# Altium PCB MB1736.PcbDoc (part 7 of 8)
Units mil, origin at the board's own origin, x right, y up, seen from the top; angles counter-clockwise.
Board outline 5905.51 x 3779.53 mil, 6 copper layers (Top Layer, L2_GND, L3_SIG, L4_VCC, L5_GND, Bottom Layer), stack 117.811 mil thick; 481 components, 387 nets, 1904 pads, 1200 vias.
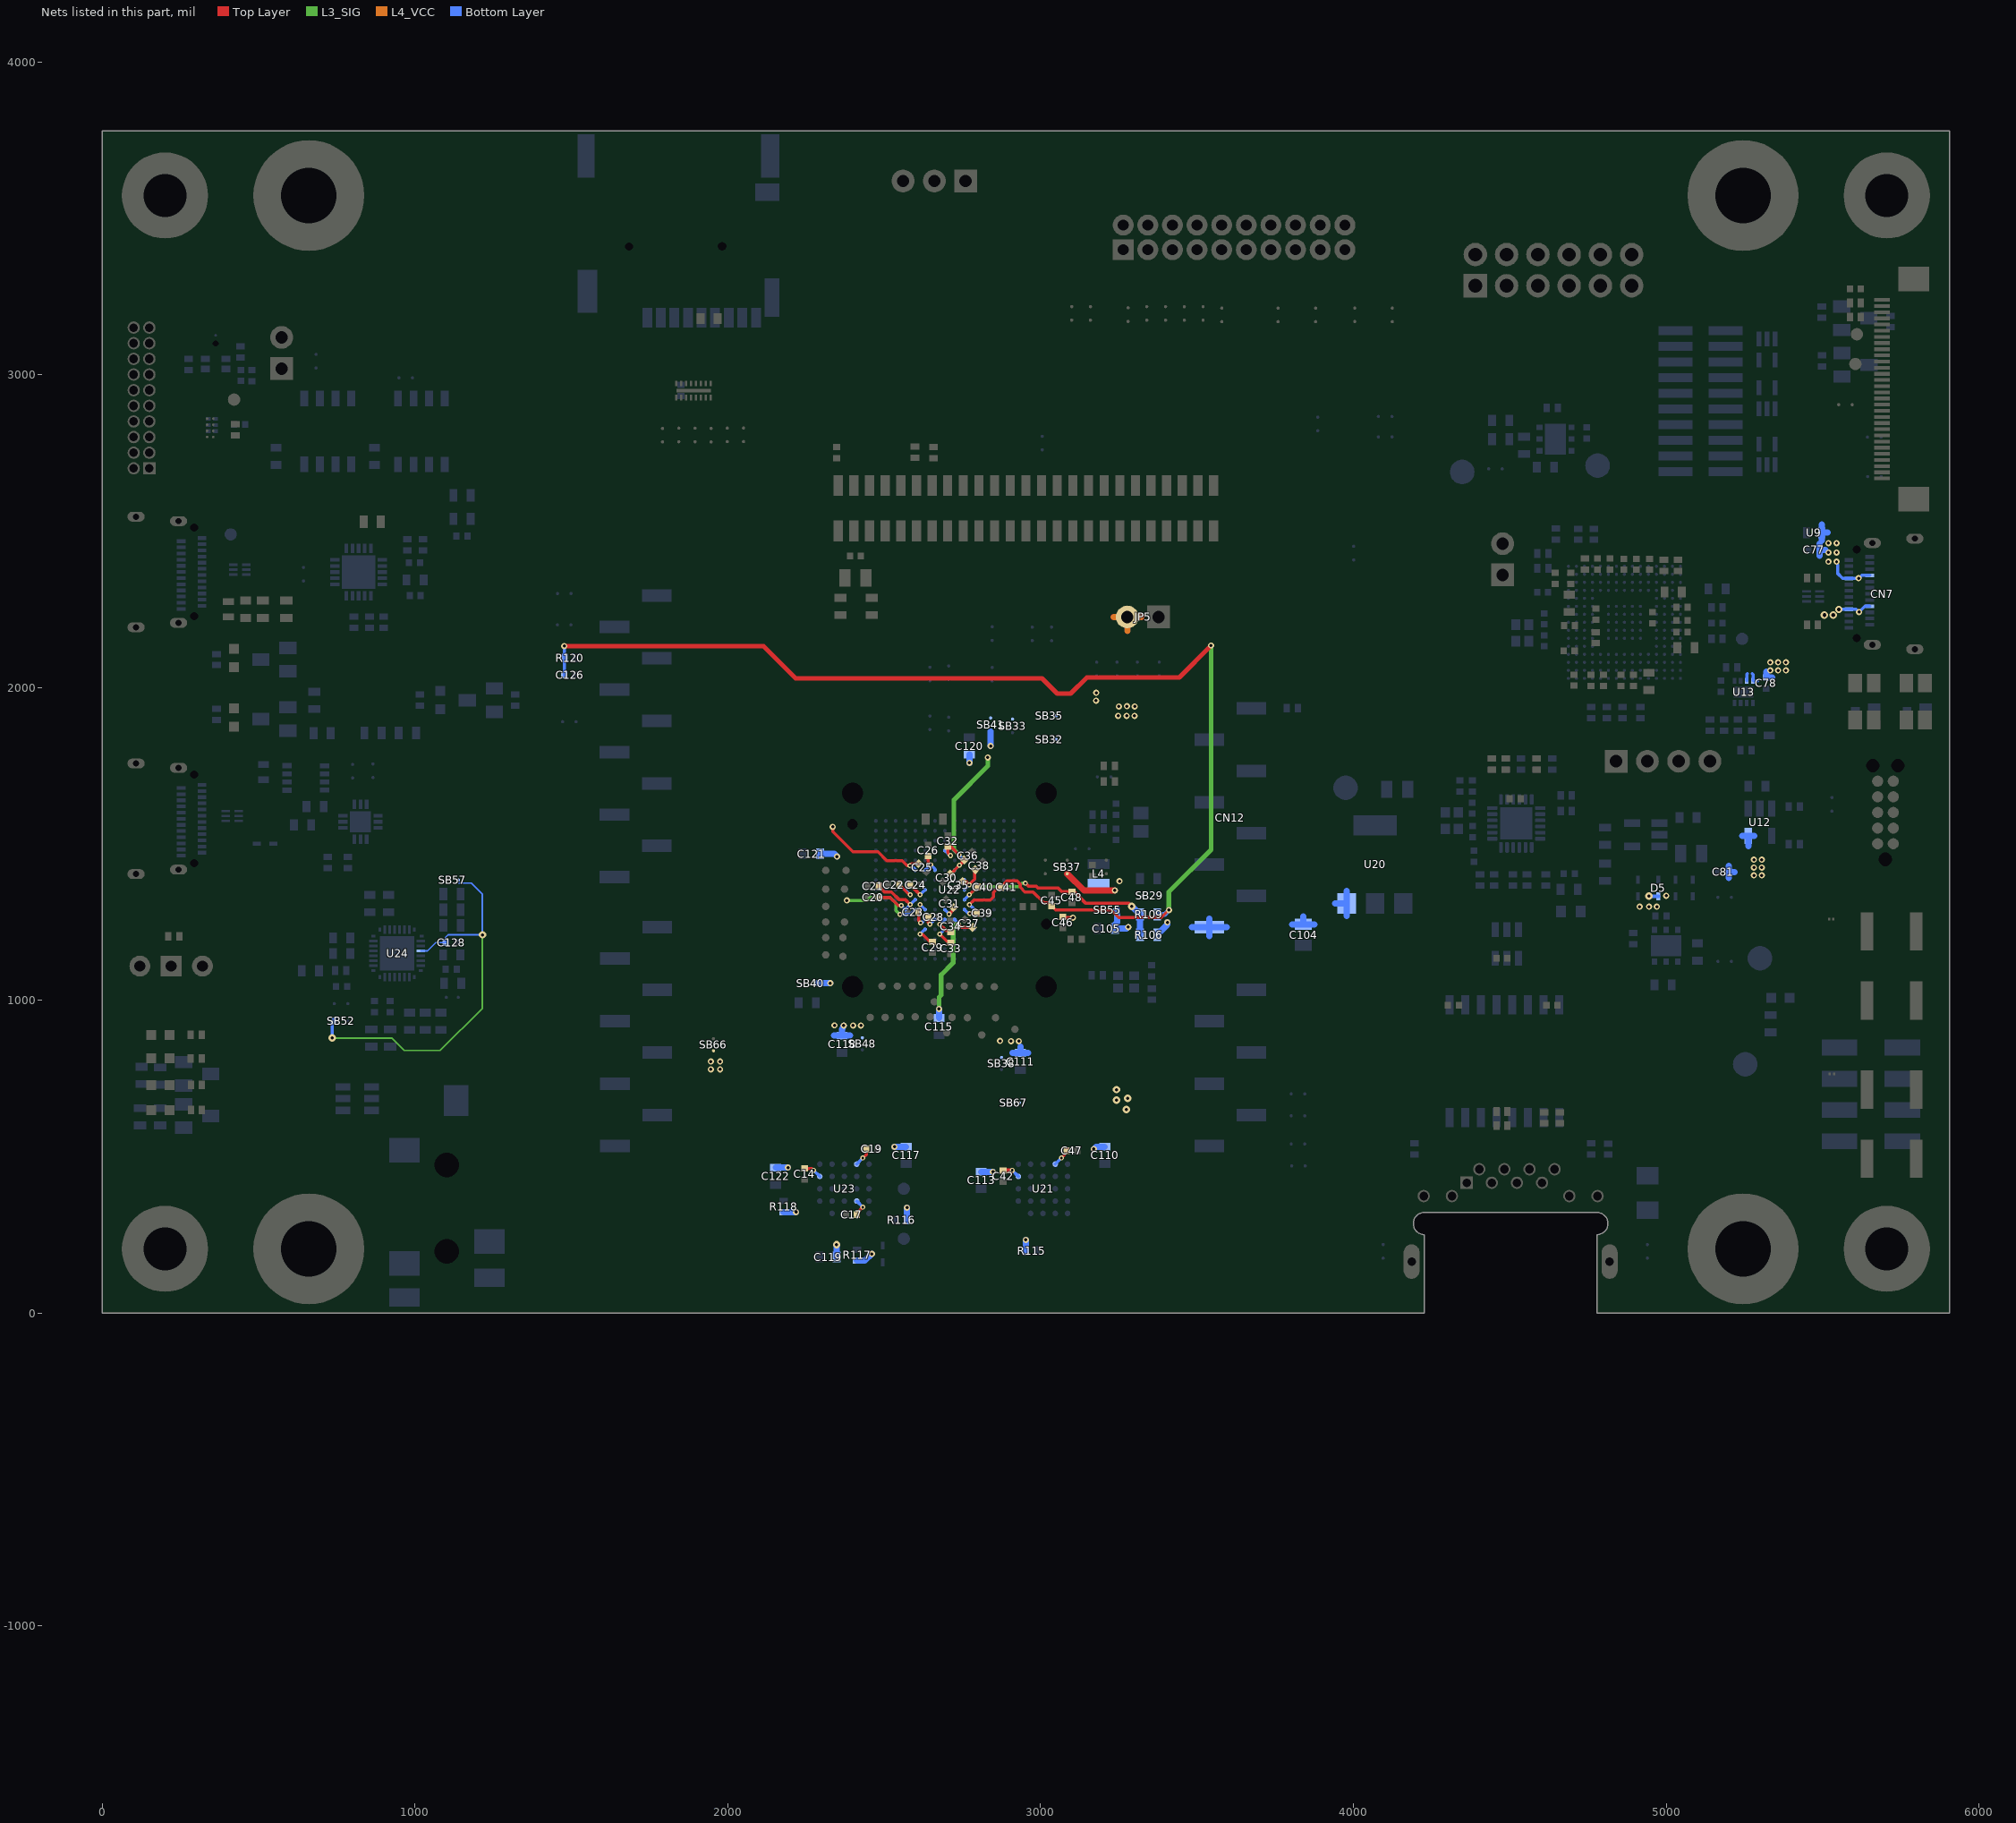
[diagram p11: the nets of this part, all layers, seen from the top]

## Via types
v1: diameter 20, hole 10, Top Layer to Bottom Layer, tented both sides, 518 vias
v2: diameter 16, hole 8, Top Layer to Bottom Layer, tented both sides, 311 vias
v3: diameter 24, hole 10, Top Layer to Bottom Layer, tented both sides, 301 vias
v4: diameter 24, hole 12, Top Layer to Bottom Layer, tented both sides, 61 vias
v5: diameter 23.62, hole 11.81, Top Layer to Bottom Layer, 9 vias

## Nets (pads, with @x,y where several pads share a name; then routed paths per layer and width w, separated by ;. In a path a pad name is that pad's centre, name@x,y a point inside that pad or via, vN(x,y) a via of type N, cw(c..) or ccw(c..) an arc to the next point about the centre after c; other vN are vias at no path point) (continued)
VBUS_STLK: C77.1 C78.1 C81.2 CN7.A4 CN7.A9 CN7.B4 CN7.B9 D5.1 U9.1 U12.5 U13.3 U13.4 | length 634.8
  Bottom Layer w10: U13.3@5257.9,2022.1 5257.88,2042.88 5260,2045 ; 5275,2045 5277.57,2042.42 U13.4@5277.58,2022.1 5292.91,2022.09 ; 5548,2392 5548,2366 5564.8,2349.2 CN7.A4@5584,2349.2 v1@5614.98,2349.21 ; v4(5552,2250) 5552.78,2250.78 CN7.A9@5584,2250.78 5607.73,2250.78 v1(5616.75,2241.75) 5635.61,2260.61 CN7.B4@5650.93,2260.62 ; v1@5616.76,2349.99 5625.83,2359.06 CN7.B9@5650.93,2359.05
  Bottom Layer w12: v3(4945,1333.42) D5.1@4975,1333.42
  Bottom Layer w20: 5200.48,1391.84 C81.2@5200.49,1410.9 ; 5200.48,1429.94 C81.2@5200.49,1410.9 ; 5218.54,1410.9 C81.2@5200.49,1410.9 ; 5242.77,1526.68 U12.5@5262.6,1526.68 ; 5262.6,1493.08 U12.5@5262.6,1526.68 ; 5282.43,1526.68 U12.5@5262.62,1526.69 ; 5320,2050.77 C78.1@5320,2032.71 5339.05,2032.72 ; 5490.49,2421.84 C77.1@5490.49,2440.9 ; 5490.49,2459.94 C77.1@5490.49,2440.9 ; 5497.38,2470.16 U9.1@5497.38,2495.9 ; 5497.38,2521.64 U9.1@5497.38,2495.9 ; 5508.55,2440.9 C77.1@5490.49,2440.9 ; 5516.23,2495.9 U9.1@5497.38,2495.9
  other v1: 4915,1300 4945,1300 4970,1300.05 5000,1335 5281,1400 5306,1400 5281,1425 5306,1425 5281,1450 5306,1450 5333,2055 5358,2055 5383,2055 5333,2081 5358,2081 5383,2081 5615.76,2349.99 5519,2403 5545,2403 5519,2432 5545,2432 5519,2462 5545,2462
  other v4: 5506,2232 5534,2232
VCAP: C25.2 C32.2 C37.2 C115.2 C120.2 C121.2 SB40.2 SB41.1 U22.D8 U22.E6 U22.F11 U22.K11 U22.L7 | length 1689.7
  Top Layer w10: v1(2335,1555) 2335,1540 2400,1475 2480,1475 2508.03,1446.97 2557.05,1446.97 2572.83,1431.18 v2(2582.28,1431.18) 2588.62,1437.52 C25.2@2609.49,1437.53 ; v2(2711.56,1463.41) 2703,1471.97 C32.2@2703,1492.3 2712.31,1492.3 v2(2738.81,1465.8) ; v2(2738,1243.5) 2748.04,1233.47 C37.2@2782.54,1233.48
  L3_SIG w10: v1(2380.5,1320) 2445,1320 2455,1330 2519,1330 2537.66,1311.34 2537.66,1287.34 v2(2550,1275)
  L3_SIG w15: v1(2674.86,973) 2675,973.14 2675,1010.76 2682,1017.76 2682,1081.99 2720,1119.99 2720,1232.89 2730.62,1243.5 v2(2738,1243.5) ; v2(2738.81,1465.8) 2722.13,1482.48 2722.13,1641.13 2831,1750 v1(2831,1777)
  Bottom Layer w10: v2(2550,1275) 2583.15,1275 U22.K11@2598.93,1290.76 ; U22.D8@2693.4,1479.73 2700.05,1473.08 2709.7,1463.41 v2(2711.56,1463.41) ; U22.L7@2724.9,1259.24 2738,1246.14 v2(2738,1243.5) ; v2(2738.81,1465.8) U22.E6@2756.37,1448.24
  Bottom Layer w12: v2(2582.28,1431.18) 2584.46,1431.18 U22.F11@2598.93,1416.75
  Bottom Layer w20: SB40.2@2286.31,1055 v1(2327,1055) ; C121.2@2294.44,1469 2340,1469 v1(2349,1460) ; v1(2674.86,973) 2675,972.86 C115.2@2675,944 ; v1(2772,1760) C120.2@2772,1786 ; v1(2840,1813.5) SB41.1@2840,1860.31
VDD_HEXASPI: C23.2 C29.2 C33.2 C34.2 C111.2 SB38.2 U22.L8 U22.L10 U22.M8 U22.M10 | length 338.2
  Top Layer w10: C23.2@2609.73,1282 2609.73,1254.8 v2(2616.3,1248.23) ; v2@2613.66,1211.01 v2@2614.66,1211.01 ; v2(2614.66,1212.01) v2@2614.66,1211.01 ; C29.2@2654,1187.73 2646.39,1187.73 2623.1,1211.01 v2@2614.66,1211.01 ; v2(2677.65,1212.01) 2699.81,1189.85 2706.65,1189.85 C33.2@2712.65,1183.85 ; v2(2677.65,1243.5) 2696.74,1224.42 2706.65,1224.42 C34.2@2712.65,1218.43
  Bottom Layer w10: v2@2613.66,1211.01 v2(2614.66,1212.01) U22.M10@2630.42,1227.77 ; v2(2616.3,1248.23) 2619.38,1248.23 U22.L10@2630.42,1259.27 ; v2(2677.65,1212.01) U22.M8@2693.39,1227.75 ; v2(2677.65,1243.5) U22.L8@2693.39,1259.25
  Bottom Layer w20: 2909.46,832.57 C111.2@2935,832.56 ; 2935,853.18 C111.2@2935,832.56 ; 2960.54,832.57 C111.2@2935,832.56
  other v1: 2905.13,869.91 2930.13,870 2870.49,870.49
VDD_HEXASPI_M: C42.2 C47.2 C110.2 C113.2 R115.2 SB67.2 U21.D1 U21.E4 | length 225.8
  Top Layer w10: v2@2907.44,455.72 v2(2908.95,457.24) ; v2(3066.42,496.6) 3082.29,512.48 C47.2@3082.29,520
  Top Layer w15: C42.2@2880,455.72 v2@2907.44,455.72
  Bottom Layer w10: v2(2908.95,457.24) U21.D1@2928.63,437.56 ; U21.E4@3046.74,476.93 v2(3066.42,496.6)
  Bottom Layer w20: C113.2@2810,452.57 v1@2847.43,452.56 ; R115.2@2952.3,199.99 v1(2952.28,234.99) ; v1(3170,525) 3177.57,532.57 C110.2@3205,532.57
  other v1: 2847.44,452.56
  other v3: 3274,652 3243,681 3278,687 3243,715
VDD_MCU: C24.2 C26.2 C28.2 C30.2 C31.2 C35.2 C36.2 C38.2 C39.2 C46.2 C105.2 JP5.2 R106.1 SB32.1 SB35.1 SB55.1 U22.F7 U22.F9 U22.F10 U22.G6 U22.H6 U22.H10 U22.K6 U22.K8 U22.K10 U22.L9 | length 850.7
  Top Layer w10: C24.2@2582.29,1370 2601.96,1350.33 2602.33,1350.33 v2(2614.66,1338) ; C26.2@2640,1462.3 2640,1442.61 v2(2648.15,1434.47) ; C28.2@2640.29,1267 2640.29,1249.36 v2(2646.15,1243.5) ; v2@2707.01,1275.91 2721.53,1290.42 C31.2@2721.54,1297.48 ; C30.2@2711.54,1404.53 2712.69,1404.52 v2(2740.63,1432.47) 2748.58,1440.42 2748.58,1442.58 C36.2@2755.5,1449.49 ; C35.2@2750.54,1380.53 2761.11,1380.52 v2(2772.12,1369.51) 2772.12,1371.11 2789,1388 2789,1417 C38.2@2790.49,1418.48 ; v2(2773,1278) 2775.11,1278 2776.11,1279 C39.2@2795.3,1279
  Top Layer w12: C46.2@3071.01,1264.72 v1(3103.28,1264.72)
  L4_VCC w20: 3232.56,2226 JP5.2@3277,2226 ; 3277,2181.56 JP5.2@3277,2226 ; 3321.44,2226 JP5.2@3277,2226
  Bottom Layer w10: v2(2614.66,1306.49) U22.K10@2630.4,1290.75 ; v2(2614.66,1338) U22.H10@2630.4,1353.74 ; U22.F10@2630.42,1416.75 v2(2648.15,1434.47) 2661.9,1420.72 U22.F9@2661.9,1416.75 ; v2(2646.15,1243.5) U22.L9@2661.92,1259.27 ; U22.K8@2693.42,1290.76 2707,1277.17 v2(2707,1275.91) ; U22.F7@2724.89,1416.73 v2(2740.63,1432.47) ; U22.K6@2756.39,1290.75 2769.15,1278 v2(2773,1278) ; U22.H6@2756.39,1353.78 v2(2772.12,1369.51) U22.G6@2756.39,1385.25
  Bottom Layer w20: 3244.37,1290 3244.37,1250.35 3237.56,1243.55 C105.2@3237.56,1230 3275,1230 v1(3280,1235) ; R106.1@3372.56,1210 3405,1242.43 v1(3405,1250)
  other v1: 3248,1910 3275.33,1910 3300.33,1910 3250,1940 3301.03,1939.94 3276.05,1940.98
VDD_OCTOSPI: C20.2 C21.2 C22.2 C118.2 SB48.2 U22.H12 U22.J11 U22.K12 | length 479.4
  Top Layer w10: C21.2@2481.74,1366 2494.86,1352.86 2500.72,1347 2522.61,1347 2546.61,1323 2566.66,1323 v2(2583.16,1306.5) ; C20.2@2481.74,1330 2518.06,1330 2544.06,1304 v2(2554.66,1304) ; C22.2@2547.74,1370 2562.86,1354.86 2579.65,1338.07 v2(2583.08,1338.07)
  Bottom Layer w10: v2(2554.66,1304) 2554.66,1303.5 2567.41,1290.75 v2(2583.16,1306.5) U22.J11@2598.92,1322.25 ; U22.H12@2567.43,1353.76 v2(2583.08,1338.07)
  Bottom Layer w20: v1(2370,920.16) 2365,908.17 C118.2@2365,887.56 ; C118.2@2365,887.56 2390.54,887.56 C118.2@2365,887.56 ; C118.2@2365,887.56 2339.46,887.56 C118.2@2365,887.56
  other v1: 2400,920 2425,920 2341.02,920.44
VDD_OCTOSPI_M: C14.2 C17.2 C19.2 C117.2 C119.2 C122.2 R116.2 R117.2 R118.2 SB66.2 U23.B4 U23.D1 U23.E4 | length 432.4
  Top Layer w10: C14.2@2245,462.73 2268.61,462.73 v2(2274.1,457.24) ; C17.2@2412.74,314.99 2412.73,320.3 v2(2431.57,339.14) ; v2(2431.57,496.6) 2442.29,507.33 C19.2@2442.29,525
  Bottom Layer w10: v2(2274.1,457.24) U23.D1@2293.78,437.56 ; U23.B4@2411.89,358.81 v2(2431.57,339.14) ; U23.E4@2411.89,476.93 v2(2431.57,496.6)
  Bottom Layer w20: C122.2@2152.52,465.75 v1(2191.85,465.75) ; R118.2@2177.76,323.19 v1(2217.76,323.19) ; C119.2@2347.56,179.99 v3(2347.56,219.99) ; R117.2@2412.52,168.21 2438.19,168.19 v1(2460,189.99) ; v1(2532.56,532.56) C117.2@2569.99,532.56 ; R116.2@2572.54,298.19 v1(2572.52,337.52)
  other v1: 1945,780.16 1975,780.16 1945,805.16 1975,805.16
VDD_SDC: L4.1 SB29.2 SB33.1 SB37.1 SB41.2 | length 174.1
  Top Layer w20: SB37.1@3085,1405.31 3138.32,1352 v1(3237,1352)
  other v1: 3252.45,1381.51 3177,1959 3178,1984
VDDA: C40.2 C48.2 R106.2 R109.2 U22.J6 | length 725.9
  Top Layer w10: v2(2772.12,1338) 2797.05,1362.92 2798.21,1362.92 C40.2@2798.3,1363 ; v2(2951.23,1375.06) 2960.28,1366 2984.94,1366 2990.72,1360.23 3044.33,1360.23 3054.78,1360.22 3067.28,1347.72 C48.2@3100,1347.72 3107.28,1347.72 3144.58,1310.42 3282.02,1310.42 v3(3291.43,1301)
  L3_SIG w10: v2(2772.12,1338) 2773,1338 2799,1364 2929.56,1364 2940.62,1375.06 v2(2951.23,1375.06)
  Bottom Layer w10: U22.J6@2756.39,1322.26 v2(2772.12,1338)
  Bottom Layer w20: v3(3291.43,1301) R109.2@3317.44,1275 R106.2@3317.44,1210
VIN: C104.2 CN12.8 U20.3 | length 453.7
  Bottom Layer w20: 3483.5,1234.25 CN12.8@3539.02,1234.25 ; 3539.02,1206.24 CN12.8@3539.02,1234.25 ; 3539.02,1262.27 CN12.8@3539.02,1234.25 ; 3594.54,1234.25 CN12.8@3539.02,1234.25 ; 3840,1269.2 C104.2@3840,1243.47 ; 3941.09,1310.11 U20.3@3978.65,1310.11 ; 3978.64,1269.61 U20.3@3978.65,1310.11 ; 3978.64,1350.61 U20.3@3978.65,1310.11 ; C104.2@3840,1243.47 3875.58,1243.48 C104.2@3840,1243.47 ; C104.2@3840,1243.47 3804.42,1243.48 C104.2@3840,1243.47
VL_AUDIO: C128.2 SB52.1 SB57.2 U24.4 | length 1299.7
  L3_SIG w5: v3(735,880) 925,880 965,840 1080,840 1215,975 v3(1215,1210)
  Bottom Layer w5: U24.4@1017.91,1158.66 1039.66,1158.66 1066,1185 C128.2@1097.28,1185 1097.28,1202.28 1105,1210 v3(1215,1210) ; 1138.39,1375 1180,1375 1215,1340 v3(1215,1210) ; v3@1215,1205 v3(1215,1210)
  Bottom Layer w10: v3(735,880) 735,928.62 SB52.1@741.22,934.84
  Bottom Layer w20: SB52.1@741.06,935 SB52.1@741.22,934.84
VREFP: C41.2 C45.2 C126.1 R109.1 R120.2 U22.K5 | length 3995.8
  Top Layer w10: v2(2772.32,1306.31) 2787.01,1321 2829.42,1321 2829.86,1321.43 2839.62,1321.43 2849.62,1331.43 2849.62,1345.03 2866.58,1362 C41.2@2873.3,1362 2873.28,1362.99 2892.32,1382.02 2924.64,1382.02 2934.23,1372.43 2934.23,1368 2934.64,1367.59 2934.64,1362.07 2949.7,1347 2975.66,1347 3010.66,1312 3025.27,1312 C45.2@3035,1302.29 3048.12,1289.16 3225.84,1289.16 3250,1265 3385.84,1265 v1(3410,1289.16)
  Top Layer w15: v1(1477,2133) 2113.71,2133 2216.71,2030 3004.01,2030 3053,1981 3096,1981 3148,2033 3443.01,2033 v1(3545,2135)
  L3_SIG w15: v1(3410,1289.16) 3410,1347 3545,1482 v1(3545,2135)
  Bottom Layer w10: C126.1@1477.03,2041.22 1477.29,2041.5 1477.29,2095 1477.29,2132.7 v1(1477,2133) ; v2(2772.32,1306.31) 2781.31,1297.32 U22.K5@2787.89,1290.75
  Bottom Layer w15: R109.1@3372.56,1275 3395.84,1275 v1(3410,1289.16)
pads on no net: CN1.3 CN1.5 CN1.7 CN1.8 CN1.9 CN1.11 CN1.13 CN1.14 CN1.15 CN1.16 CN1.17 CN1.18 CN2.41 CN2.42 CN2.44 CN2.46 CN2.48 CN4.9 CN4.10 CN5.7 CN5.9 CN5.11 CN5.12 CN5.13 CN6.18 CN6.31 CN6.32 CN7.0 CN7.A2 CN7.A3 CN7.A8 CN7.A10 CN7.A11 CN7.B2 CN7.B3 CN7.B8 CN7.B10 CN7.B11 CN8.7 CN13.NPTH1 CN13.NPTH2 CN16.5 CN16.7 CN16.MT1 CN16.MT2 CN17.0 CN17.A2 CN17.A3 CN17.A8 CN17.A10 CN17.A11 CN17.B2 CN17.B3 CN17.B8 CN17.B10 CN17.B11 CN18.0 CN18.A2 CN18.A3 CN18.A8 CN18.A10 CN18.A11 CN18.B2 CN18.B3 CN18.B8 CN18.B10 CN18.B11 U1.6 U3.2 U14.A1 U14.A2 U14.A3 U14.A4 U14.A5 U14.A8 U14.A9 U14.A11 U14.A12 U14.A13 U14.B1 U14.B2 U14.B3 U14.B4 U14.B5 U14.B6 U14.B7 U14.B8 U14.B9 U14.B10 U14.B11 U14.B12 U14.B14 U14.B15 U14.C2 U14.C3 U14.C4 U14.C12 U14.C13 U14.C14 U14.C15 U14.D1 U14.D2 U14.D3 U14.D11 U14.D13 U14.D14 U14.E1 U14.E2 U14.E3 U14.E4 U14.E12 U14.E13 U14.E14 U14.E15 U14.F1 U14.F4 U14.F14 U14.G4 U14.G14 U14.G15 U14.H2 U14.H3 U14.H4 U14.H14 U14.J2 U14.J3 U14.J4 U14.K1 U14.K2 U14.K3 U14.K12 U14.K13 U14.K14 U14.K15 U14.L1 U14.L12 U14.L13 U14.L14 U14.L15 U14.M2 U14.M3 U14.M4 U14.M7 U14.M12 U14.M13 U14.M14 U14.M15 U14.N2 U14.N4 U14.N6 U14.N7 U14.N11 U14.N13 U14.N14 U14.N15 U14.P2 U14.P4 U14.P5 U14.P6 U14.P7 U14.P8 U14.P9 U14.P10 U14.P11 U14.P12 U14.P13 U14.P14 U14.P15 U14.R2 U14.R3 U14.R6 U14.R7 U14.R8 U14.R9 U14.R10 U14.R11 U14.R12 U14.R13 U15.3 U22.NPTH1 U22.NPTH2 U22.PTH1 U22.PTH2 U22.PTH3 U22.PTH4 U23.A2 U23.A3 U23.B1 U23.B5 U24.16 U24.17 U24.18 U24.25 U24.26 U27.1 U27.3 U27.11 U33.4 U33.5 U33.12 U33.13

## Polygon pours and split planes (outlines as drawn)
1V8_AUDIO on L3_SIG "TOP-No Net" (solid, pour order 486): 18 vertices, not listed, extent 680,900 1135,1260
VBUS_STLK on L3_SIG "L3_SIG-VBUS_STLK" (solid, remove dead copper, pour order 272): 265 vertices, not listed, extent 5265,1374.99 5730,2485.97
VBUS2 on L3_SIG "Bottom Layer-VCC1V0" (solid, remove dead copper, pour order 478): 281,1697 242,1658 242,1497.78 258.78,1481 376,1481 388,1493 388,1691 382,1697
VDD_SDC on L3_SIG "Bottom Layer-VCC1V0" (solid, remove dead copper, pour order 464): 17 vertices, not listed, extent 3160,1340 3294,2014
VBUS1 on L3_SIG "L3_SIG-VBUS1" (solid, remove dead copper, pour order 264): 190 vertices, not listed, extent 237,2180 1308,2645.91
NetSB32_2 on L3_SIG "L3_SIG-NETSB32_2" (solid, pour order 266): 623 vertices, not listed, extent 2620,1296 2748.98,1409.98
5V_STLK on L3_SIG "L3_SIG-5V_STLK" (solid, remove dead copper, pour order 268): 369 vertices, not listed, extent 5056,830 5875,1965
VDD_HEXASPI_M on L3_SIG "L3_SIG-VDD_HEXASPI_M" (solid, pour order 274): 3281,219.99 2845,219.99 2815,249.99 2815,712.89 2850.58,748.47 3265.54,748.47 3314,700 3314.01,253.01 3281,219.99
VDD_OCTOSPI on L3_SIG "L3_SIG-VDD_OCTOSPI" (solid, pour order 276): 801 vertices, not listed, extent 2327,887.56 2686,1351.98
5V_USB_SNK on L3_SIG "L3_SIG-5V_USB_SNK" (solid, pour order 270): 1109 vertices, not listed, extent 497.76,19.99 5885,1922
5V on Top Layer "TOP-No Net" (solid, pour order 479): 2526,2268 2535,2259 2535,2224.99 2524,2214 2397,2214 2386,2225 2386,2256 2398,2268
5V_UCPD on Top Layer "TOP-No Net" (solid, pour order 474): 39 vertices, not listed, extent 850,1271 4871,3702
VDD_OCTOSPI_M on Top Layer "TOP-VDD_OCTOSPI_M" (solid, pour order 278): 58 vertices, not listed, extent 1904,761 1996,849.84
VBUS1 on Top Layer "TOP-VBUS1" (solid, pour order 280): 33 vertices, not listed, extent 364,2260.91 552.76,2325.91
VBUS1 on Top Layer "TOP-VBUS1 1" (solid, pour order 282): 797.1,2510.91 788,2520 788,2600 795,2607 848,2607 852.74,2602.25 852.74,2556.6 816.58,2556.6 816.58,2510.91
NetC16_1 on Top Layer "TOP-NETC16_1" (solid, pour order 284): 29 vertices, not listed, extent 2275,2275 2415,2535
NetC150_1 on Top Layer "TOP-NETC150_1" (solid, pour order 288): 908.94,2505.91 908.94,2556.6 872.76,2556.6 872.76,2600.91 822.76,2650.91 822.76,2845.76 842,2865 901,2865 921,2845 921,2652.67 927.76,2645.91 927.76,2515.91 917.76,2505.91
5V on Top Layer "TOP-5V" (solid, pour order 290): 1280,2843 1301,2864 1406,2864 1615,2655 1615,2375 1595,2355 1505,2355 1475,2385 1475,2580 1280,2775
VBUS_STLK on Top Layer "TOP-VBUS_STLK" (solid, pour order 292): 78 vertices, not listed, extent 4880,1280 5330,1462.5
1V8 on Top Layer "TOP-1V8" (solid, pour order 294): 131 vertices, not listed, extent 1892,869 2020,970
NetC16_2 on Top Layer "TOP-NETC16_2" (solid, pour order 286): 49 vertices, not listed, extent 2420.02,2275 2530,2445
5V_UCPD on Bottom Layer "TOP-No Net" (solid, pour order 476): 23 vertices, not listed, extent 4789,415 5840,1359
5V_UCPD on Bottom Layer "TOP-No Net" (solid, pour order 472): 931,3037 950,3018 950,2972 932,2954 868,2954 863,2959 863,3029 871,3037
VDD_SDC on Bottom Layer "TOP-No Net" (solid, pour order 468): 3264,1392 3294,1362 3327.72,1362 3335.04,1354.68 3335.04,1321.02 3322.02,1308 3286,1308 3267,1327 3132,1327 3122,1337 3122,1382 3132,1392
VDD_SDC on Bottom Layer "TOP-No Net" (solid, pour order 466): 3189,2002 2898,2002 2873,1977 2826,1977 2818,1969 2818,1897.27 2820.31,1894.96 2916.96,1894.96 2963,1941 3188,1941 3196,1949 3196,1995
T_VCC on Bottom Layer "TOP-No Net" (solid, pour order 462): 5282,1245 5359,1245 5373,1231 5373,1075 5353,1055 5213,1055 5201,1067 5201,1115 5210,1124 5210,1145 5264.76,1199.76 5264.76,1225.24
5V_USB_SNK on Bottom Layer "BOTTOM-5V_USB_SNK" (solid, pour order 350): 48 vertices, not listed, extent 695,1690 850,1920
5V_VIN on Bottom Layer "BOTTOM-5V_VIN" (solid, pour order 342): 96 vertices, not listed, extent 3770,1348.61 4155,1880
5V on Bottom Layer "BOTTOM-5V" (solid, pour order 336): 46 vertices, not listed, extent 4858,485 5635,1190
GND on Bottom Layer "BOTTOM-GND 4" (solid, pour order 334): 42 vertices, not listed, extent 5135,1870 5500,2005
NetC150_1 on Bottom Layer "BOTTOM-NETC150_1" (solid, pour order 322): 33 vertices, not listed, extent 732.14,2755 1162.76,3127
VIN on Bottom Layer "BOTTOM-VIN" (solid, pour order 296): 30 vertices, not listed, extent 3475,1150 4005,1420
VBUS_STLK on Bottom Layer "TOP-No Net" (solid, pour order 480): 5496,2219 5548,2219 5567,2238 5567,2259 5562,2264 5542.08,2264 5528,2249.92 5494.92,2249.92 5490,2245 5490,2223
VDD_MCU on Bottom Layer "BOTTOM-VDD_MCU" (solid, pour order 298): 30 vertices, not listed, extent 3059.72,1812.5 3317,1977
VDD_HEXASPI on Bottom Layer "BOTTOM-VDD_HEXASPI" (solid, pour order 300): 89 vertices, not listed, extent 2830,814.91 2975,955
VBUS1 on Bottom Layer "BOTTOM-VBUS1" (solid, pour order 304): 1167.76,2570.91 1162.76,2575.91 1162.76,2589.3 1196.18,2589.3 1196.18,2640.69 1162.76,2640.69 1162.76,2645.91 1173.85,2657 1281,2657 1294,2644 1294,2583 1281.91,2570.91
NetSB32_2 on Bottom Layer "BOTTOM-NETSB32_2" (solid, pour order 308): 101 vertices, not listed, extent 2890,1795 3010,1865
NetQ5_1 on Bottom Layer "BOTTOM-NETQ5_1" (solid, pour order 310): 138 vertices, not listed, extent 617.76,2430.91 832.76,2734.19
NetQ4_1 on Bottom Layer "BOTTOM-NETQ4_1" (solid, pour order 312): 363 vertices, not listed, extent 798.77,2475.91 1137.76,2735.91
NetC93_2 on Bottom Layer "BOTTOM-NETC93_2" (solid, pour order 314): 40 vertices, not listed, extent 4529.84,2728.75 4604.7,2770
NetC93_2 on Bottom Layer "BOTTOM-NETC93_2 1" (solid, pour order 316): 36 vertices, not listed, extent 4482,2660.48 4604.7,2769
NetC90_2 on Bottom Layer "BOTTOM-NETC90_2" (solid, pour order 318): 51 vertices, not listed, extent 4645,2825 4775,2955
NetC86_2 on Bottom Layer "BOTTOM-NETC86_2" (solid, pour order 320): 75 vertices, not listed, extent 4991,1084 5158.47,1144
NetC150_1 on Bottom Layer "BOTTOM-NETC150_1 1" (solid, pour order 324): 1040,2760 1032.14,2767.85 1032.14,2893.99 1063.81,2893.99 1063.81,2950 1076.19,2950 1076.19,2893.99 1113.81,2893.99 1113.81,2950 1131,2950 1132.34,2951.33 1135,2948.67 1135,2780 1115,2760 1040,2760
GND on Bottom Layer "BOTTOM-GND" (solid, pour order 326): 32 vertices, not listed, extent 3780,1110 4265,1780
GND on Bottom Layer "BOTTOM-GND 1" (solid, pour order 328): 72 vertices, not listed, extent 5055.25,1163.08 5135,1265
GND on Bottom Layer "BOTTOM-GND 2" (solid, pour order 330): 22 vertices, not listed, extent 5025,1440 5170,1630
GND on Bottom Layer "BOTTOM-GND 3" (solid, pour order 332): 38 vertices, not listed, extent 5295.02,1655 5405,1740
5V on Bottom Layer "BOTTOM-5V 2" (solid, pour order 340): 49 vertices, not listed, extent 642.76,2754 1440,3290
5V_STLK on Bottom Layer "BOTTOM-5V_STLK" (solid, pour order 344): 17 vertices, not listed, extent 5200,1575.01 5275,1740
5V_STLK on Bottom Layer "BOTTOM-5V_STLK 1" (solid, pour order 346): 70 vertices, not listed, extent 5252.76,1865 5414.98,1954.98
5V_STLK on Bottom Layer "BOTTOM-5V_STLK 2" (solid, pour order 348): 5682.61,822.39 5670,835 5670,930 5680,940 5860,940 5870,930 5870,830 5862.39,822.39 5818.12,822.39 5818.12,881.59 5691.92,881.59 5691.92,822.39 5682.61,822.39
5V_USB_SNK on Bottom Layer "BOTTOM-5V_USB_SNK 1" (solid, pour order 352): 78 vertices, not listed, extent 5155.02,1165 5250,1354.98
5V_USB_SNK on Bottom Layer "BOTTOM-5V_USB_SNK 2" (solid, pour order 354): 5843.31,615 5843.29,615.01 5818.12,615.01 5818.12,681.59 5691.92,681.59 5691.92,615.01 5679.98,615.01 5665,630 5665,695 5680,710 5880,710 5885,705 5885,620 5880,615 5843.31,615
VBUS_STLK on Bottom Layer "BOTTOM-VBUS_STLK" (solid, pour order 356): 25 vertices, not listed, extent 5477.76,2378 5562,2533
VBUS_STLK on Bottom Layer "BOTTOM-VBUS_STLK 1" (solid, pour order 358): 5289.5,2025.01 5289.5,2037.95 5255,2037.95 5255,2075 5275,2095 5389.01,2095 5398.75,2085.25 5398.75,2031.25 5390.51,2023 5337.04,2023 5337.04,2048.77 5302.96,2048.77 5302.96,2025.01
VBUS_STLK on Bottom Layer "BOTTOM-VBUS_STLK 2" (solid, pour order 360): 20 vertices, not listed, extent 5190,1375 5330.51,1555
T_VCC on Bottom Layer "BOTTOM-3V3 1" (solid, pour order 364): 49 vertices, not listed, extent 4484,2827.65 4624.98,2957
3V3_STLK on Bottom Layer "BOTTOM-3V3_STLK" (solid, pour order 366): 47 vertices, not listed, extent 4900,1562.74 5055,1690
1V8 on Bottom Layer "BOTTOM-1V8" (solid, pour order 368): 162 vertices, not listed, extent 2390,710 2455,838.94
1V8 on Bottom Layer "BOTTOM-1V8 1" (solid, pour order 370): 164 vertices, not listed, extent 2846,660.67 2906,776
1V8 on Bottom Layer "BOTTOM-1V8 2" (solid, pour order 372): 221 vertices, not listed, extent 4242,2623 4454,2759
NetC85_2 on Bottom Layer "BOTTOM-NETC85_2" (solid, pour order 374): 30 vertices, not listed, extent 4890,1370 5095,1499.98
NetD3_1 on Bottom Layer "BOTTOM-NETD3_1" (solid, pour order 376): 147 vertices, not listed, extent 5060,1290 5158.46,1355
NetR83_1 on Bottom Layer "BOTTOM-NETR83_1" (solid, pour order 378): 80 vertices, not listed, extent 4770,1420 4911.95,1510
T_PWR_EN on Bottom Layer "BOTTOM-T_PWR_EN" (solid, pour order 380): 20 vertices, not listed, extent 5307.76,1465 5405,1570
VDD_HEXASPI_M on Bottom Layer "BOTTOM-VDD_HEXASPI_M" (solid, pour order 382): 60 vertices, not listed, extent 2924.87,634 3299.01,732
VDD_OCTOSPI on Bottom Layer "BOTTOM-VDD_OCTOSPI" (solid, pour order 384): 93 vertices, not listed, extent 2320,875 2465,942
5V on Bottom Layer "BOTTOM-5V 1" (solid, pour order 338): 73 vertices, not listed, extent 1475,2215 2540,2475
UCPD_SOURCE1 on Bottom Layer "TOP-No Net" (solid, pour order 482): 516,3064 622,3064 651,3035 707,3035 717,3025 717,2772 709,2764 611,2764 598,2751 527,2751 502,2776 502,3053 508,3059
VBUS2 on Bottom Layer "TOP-No Net" (solid, pour order 484): 560,1795 660,1795 674.98,1780.01 674.98,1615.3 660,1600.32 594.68,1600.32 559.32,1635.68 357.98,1635.68 348.67,1645 348.67,1701.82 367.76,1720.91 540,1720.91 555,1735.91 555,1790
1V8 on L4_VCC "L4_VCC-1V8" (solid, pour order 426): 1464 vertices, not listed, extent 1025,640 5575,3180
T_VCC on L4_VCC "L4_VCC-3V3 8" (solid, pour order 460): 146 vertices, not listed, extent 3908.41,3414.7 3958.25,3464.55
T_VCC on L4_VCC "L4_VCC-3V3 7" (solid, pour order 458): 146 vertices, not listed, extent 3829.67,3414.7 3879.51,3464.55
T_VCC on L4_VCC "L4_VCC-3V3 6" (solid, pour order 456): 146 vertices, not listed, extent 3750.93,3414.7 3800.77,3464.55
T_VCC on L4_VCC "L4_VCC-3V3 5" (solid, pour order 454): 146 vertices, not listed, extent 3672.19,3414.7 3722.03,3464.55
T_VCC on L4_VCC "L4_VCC-3V3 4" (solid, pour order 452): 146 vertices, not listed, extent 3593.45,3414.7 3643.29,3464.55
T_VCC on L4_VCC "L4_VCC-3V3 3" (solid, pour order 450): 146 vertices, not listed, extent 3514.71,3414.7 3564.55,3464.55
T_VCC on L4_VCC "L4_VCC-3V3 2" (solid, pour order 448): 146 vertices, not listed, extent 3435.97,3414.7 3485.81,3464.55
T_VCC on L4_VCC "L4_VCC-3V3 1" (solid, pour order 446): 141 vertices, not listed, extent 3285.48,3421.7 3328.33,3464.55
T_VCC on L4_VCC "L4_VCC-3V3" (solid, pour order 444): 146 vertices, not listed, extent 3357.23,3414.7 3407.07,3464.55
VDD_MCU on L4_VCC "L4_VCC-VDD_MCU" (solid, pour order 440): 1749 vertices, not listed, extent 2535,870 3420,2255
NetSB32_2 on L4_VCC "L4_VCC-NETSB32_2" (solid, pour order 436): 506 vertices, not listed, extent 2380,1350 3035,1865
VCAP on L4_VCC "L4_VCC-VCAP" (solid, pour order 434): 428 vertices, not listed, extent 2155,845 2865,1950
5V on L4_VCC "L4_VCC-5V" (solid, pour order 430): 1079 vertices, not listed, extent 2375,734.99 4205.01,2560
3V3_STLK on L4_VCC "L4_VCC-3V3_STLK" (solid, pour order 428): 813 vertices, not listed, extent 4210,1635 5390,2425
NetC49_2 on L4_VCC "L4_VCC-NETC49_2" (solid, pour order 432): 654 vertices, not listed, extent 4210,1030 4715,1580
VDD_HEXASPI on L4_VCC "L4_VCC-VDD_HEXASPI" (solid, pour order 438): 1060 vertices, not listed, extent 2535.02,845 2975,1267.48
VDD_OCTOSPI_M on L4_VCC "L4_VCC-VDD_OCTOSPI_M" (solid, pour order 442): 234 vertices, not listed, extent 1825,174.99 2665,889.98
5V on L4_VCC "TOP-No Net" (solid, pour order 424): 3925.18,899.21 3925.18,692.82 4045,573 4958,573 4993,608 4993,941 4935,999 4316.82,999 4205.01,1110.82 3947.82,1110.82 3923,1086
T_VCC on L4_VCC "L4_VCC-3V3 9" (solid, remove dead copper, pour order 470): 828 vertices, not listed, extent 20.04,20.03 5885.48,3759.49
GND on L2_GND "L2_GND-GND 9" (solid, remove dead copper, pour order 204): 268 vertices, not listed, extent 20,19.99 5885.51,3759.52
GND on L5_GND "L5_GND-GND 9" (solid, remove dead copper, pour order 250): 268 vertices, not listed, extent 20,19.99 5885.51,3759.52

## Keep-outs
Keep-Out Layer:
  lines w4: 4148.42,0 0,0 0,3779.53 5905.51,3779.53 5905.51,0 4778.35,0

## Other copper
Top Layer:
  pour cut-out: 4232.76,941.73 4732.76,941.73 4732.76,670.07 4232.76,670.07
  text "1" at 1022.89,3725 h31.5
  text ".Layer_Name" at 1230.19,-1194.98 h118.11
  text ".GTL" at 2871.72,-1194.98 h118.11
L2_GND:
  pour cut-out: 4232.76,941.73 4732.76,941.73 4732.76,670.07 4232.76,670.07
  text "2" at 1048.09,3725 h31.5
  text ".Layer_Name" at 1315,-1211 h118.11
  text ".G1" at 2909,-1219 h118.11
L3_SIG:
  pour cut-out: 4232.76,940.49 4731.51,940.49 4732,940 4732,672.78 4732.76,672.02 4730.82,670.07 4232.76,670.07
  text "3" at 1084.51,3725 h31.5
  text ".Layer_Name" at 1291,-1186 h118.11
  text ".G2" at 2905,-1206 h118.11
L4_VCC:
  pour cut-out: 4232.76,941.73 4732.76,941.73 4732.76,673 4235.69,673 4232.76,670.07
  text "4" at 1119.98,3725 h31.5
  text ".Layer_Name" at 1284,-1180 h118.11
  text ".G3" at 2894,-1193 h118.11
L5_GND:
  pour cut-out: 4232.76,941.73 4732.76,941.73 4730.82,939.78 4730.82,670.07 4232.76,670.07
  text "5" at 1153.76,3725 h31.5
  text ".Layer_Name" at 1284,-1188 h118.11
  text ".G4" at 2906,-1201 h118.11
Bottom Layer:
  text "6" at 1211.63,3725 h31.5
  text ".GBL" at 2430.65,-1196.23 h118.11
  text ".Layer_Name" at 4057.18,-1196.23 h118.11
Multi-Layer:
  pour cut-out: 1010.06,3779.33 1010.06,3700.59 1226.59,3700.59 1226.59,3779.33

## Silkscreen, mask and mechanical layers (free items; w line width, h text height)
Top Overlay:
  lines w5: 185,3275 65,3275 65,3330 185,3330 185,3320 185,3287.5 185,3276.25 ; 3155,2750 3035,2750 3035,2805 3155,2805 3155,2795 3155,2762.5 3155,2751.25 ; 5,1170 190,1170 190,1185 190,1205 190,1231.42 5,1231.42 5,1170 ; 255,1820 310,1820 310,1970 298.75,1970 266.25,1970 255,1970 255,1820 ; 255,2000 310,2000 310,2150 298.75,2150 266.25,2150 255,2150 255,2000 ; 2918,3629 2918,3695.42 3158,3695.42 3158,3629 2918,3629 ; 4115,3641 4115,3707.42 4288.58,3707.42 4290,3706 4290,3641 4115,3641 ; 5498.58,1480 5498.58,1610 5555,1610 5555,1480 5498.58,1480 ; 5625,365 5625,420 5782.76,420 5782.76,365 5625,365 ; 5630,835 5630,891.42 5790,891.42 5790,835 5630,835 ; 5640,2165 5696.42,2165 5696.42,2295 5696.42,2305 5664.1,2305 5640,2305 5640,2165 ; 5645,3355 5645,3410 5890,3410 5890,3355 5645,3355 ; 5830,2070 5830,2445 5896.42,2445 5896.42,2070 5830,2070
  lines w6: 2375,985 2365,995 ; 2375,1005 2365,995 ; 2495,1010 2460,1010 ; 2660,1030 2670,1030 2670,1045 2670,1075 2460,1075 2460,1010 ; 2365,995 2430,995 2445,1010 2460,1010
  lines w19.68: 4050,3381.89 4295,3381.89
  text "PMOD" at 4125,3656 h60
  text "STMOD+" at 2928,3642 h60
  text "CAMERA" at 5655,3365 h60
  text "MIC" at 75,3285 h60
  text "LCD" at 3045,2760 h60
  text "COM" at 5686.42,2175 h60 r90
  text "PWR_STATUS" at 5880,2080 h60 r90
  text "USB1" at 300,2010 h60 r90
  text "USB2" at 300,1830 h60 r90
  text "J" at 290,1760 h700 r90
  text "TAG" at 5545,1490 h60 r90
  text "BOOT0" at 10,1180 h60
  text "1<->0" at 170,1000 h50
  text "NRST" at 5640,845 h60
  text "USER" at 5635,375 h60
  text ".Layer_Name" at 1230.19,-1194.98 h118.11
  text ".GTO" at 2871.72,-1194.98 h118.11
Bottom Overlay:
  rectangle: 2203.87,2924.83 3188.13,3279.17
  rectangle: 3312.87,2928.83 4297.13,3283.17
  lines w5: 830,980 830,805 1115,805 1115,740 1220,740 1365,740 1365,985 945,985 945,995 ; 840,1020 905,1020 ; 2810,3684.83 2810,3697.41 2810,3722.59 2810,3735.17 ; 2810,3685 2680,3685 2680,3735.34 2810,3735.34 ; 3075,1490 3075,1520 3205,1520 3205,1470 3240,1470 3240,1325 3280,1325 3280,1130 3125,1130 ; 3080,1365 3080,1355 3125,1355 3125,1130 ; 4352.41,2325 4365,2325 4390.17,2325 4402.76,2325 ; 4352.59,2325 4352.59,2480 4367.59,2480 4402.93,2480 4402.93,2325 ; 4375,2529.83 4375,2542.41 4375,2567.59 4375,2580.17 ; 4375,2530 4275,2530 4275,2555.34 4275,2580.34 4375,2580.34 ; 4835,1829.66 4835,1855 4835,1880 ; 4835,1830 5070,1830 ; 4835,1880.34 5070,1880.34 ; 4863.83,2876 4876.41,2876 4901.59,2876 4914.17,2876 ; 4864,2876 4864,3091 4914.34,3091 4914.34,2876 ; 5070,1829.83 5070,1842.41 5070,1867.59 5070,1880.17 ; 5120,1370 5270,1370 5470,1370 5470,1290 5280,1290 5280,1370 ; 5210,3234.83 5210,3247.41 5210,3272.59 5210,3285.17 ; 5210,3235 5017,3235 5017,3285.34 5210,3285.34 ; 5556,999 5461,999 5461,1052 5556,1052 5556,1000 ; 5701,2525.66 5701,2551 5701,2576 ; 5701,2526 5846,2526 ; 5701,2576.34 5846,2576.34 ; 5846,2525.83 5846,2538.41 5846,2563.59 5846,2576.17 ; 3095,975 3095,1130 3125,1130 ; 3095,975 3095,640 3240,640 3240,975 3225,975 3095,975 ; 190,1830 340,1830 340,1885 190,1885 190,1873.75 190,1841.25 190,1830 ; 210,2615 210,2626.25 210,2658.75 210,2670 360,2670 360,2615 210,2615 ; 1320,235 1320,390 1320,430 1385,430 1385,235 1320,235 ; 1420,3360 1475,3360 1475,3645 1463.75,3645 1431.25,3645 1420,3645 1420,3360 ; 2918,3628 2918,3694.42 3158,3694.42 3158,3628 2918,3628 ; 3925,1780 4125,1780 4125,1845 3935,1845 3925,1845 3925,1780 ; 4091,269 4156,269 4156,574 4091,574 4091,424 4091,269 ; 4115,3639 4115,3704 4116.42,3705.42 4290,3705.42 4290,3639 4115,3639 ; 4880,1315 5120,1315 5120,1420 4880,1420 4880,1315 ; 5090,805.91 5090,831.25 5090,856.25 5180,856.25 5180,805.91 5090,805.91 ; 5360,1085 5465,1085 5465,1102.41 5465,1135 5360,1135 5360,1115.34 5360,1085
  text "MDC" at 2800,3690 h60
  text "PMOD" at 4280,3654 h60
  text "STMOD+" at 3148,3643 h60
  text "MB1736D" at 4050,3595 h120
  text "H" at 4750,3515 h551.18
  text "PC1" at 2590,3505 h60
  text "PB2" at 2810,3505 h60
  text "MICRO-SD" at 1430,3370 h60 r270
  text "MIPI20" at 5193,3241 h60
  text "E" at 1241,3202 h551.18
  text "GND" at 609,3190 h30
  text "UCPD" at 603,2907 h30
  text "DEBUG" at 4869,2891 h60 r270
  text "USB1" at 350,2625 h60
  text "1V8" at 4370,2535 h60
  text "STLK" at 5841,2531 h60
  text "F" at 3335,2393 h551.18
  text "G" at 2580,2340 h551.18
  text "S" at 3955,2335 h450
  text "NRST" at 4357.59,2330 h60 r270
  text "D15" at 1634,2286 h60
  text "D14" at 1630,2230 h60
  text "VDD_MCU" at 3481,2106 h60 r270
  text "D13" at 1641,1887 h60
  text "USB2" at 330,1840 h60
  text "Reserved" at 5065,1835 h60
  text "D12" at 1640,1830 h60
  text "5V_VIN" at 4115,1800 h60
  text "IOREF" at 3895,1785 h60
  text "NRST" at 3895,1710 h60
  text "D11" at 1640,1680 h60
  text "D10" at 1640,1630 h60
  text "3V3" at 3835,1620 h60
  text "5V" at 3814,1551 h60
  text "D9" at 1559,1481 h60
  text "GND" at 3785,1395 h60
  text "D8" at 1560,1380 h60
  text "GND" at 3790,1260 h60
  text "D7" at 1569,1204 h60
  text "VIN" at 3785,1195 h60
  text "D6" at 1571,1120 h60
  text "3V3" at 5455,1090 h60
  text "D5" at 1569,1025 h60
  text "A0" at 3800,1015 h60
  text "5V" at 5541,1006 h60
  text "D4" at 1569,945 h60
  text "A1" at 3800,910 h60
  text "A2" at 3800,820 h60
  text "D3" at 1568,815 h60
  text "5V" at 5165,810 h60
  text "STLK" at 5460,800 h60 r315
  text "A3" at 3805,740 h60
  text "D2" at 1569,739 h60
  text "5VIN" at 5455,700 h60 r315
  text "D1" at 1564,624 h60
  text "USB2" at 5450,610 h60 r315
  text "A4" at 3766,564 h60
  text "D0" at 1565,544 h60
  text "USB1" at 5460,505 h60 r315
  text "A5" at 3767,495 h60
  text "ETHERNET" at 4106,279 h60 r270
  text "AUDIO" at 1335,250 h60 r270
  text "I" at 3742,109 h551.18
  text "C" at 1923,85 h551.18
  text ".GBO" at 2430.65,-1196.23 h118.11
  text ".Layer_Name" at 4057.18,-1196.23 h118.11
Top Paste:
  text ".Layer_Name" at 1230.19,-1194.98 h118.11
  text ".GTP" at 2871.72,-1194.98 h118.11
Bottom Paste:
  text ".GBP" at 2430.65,-1196.23 h118.11
  text ".Layer_Name" at 4057.18,-1196.23 h118.11
Top Solder:
  text ".Layer_Name" at 1230.19,-1194.98 h118.11
  text ".GTS" at 2871.72,-1194.98 h118.11
Bottom Solder:
  text ".GBS" at 2430.65,-1196.23 h118.11
  text ".Layer_Name" at 4057.18,-1196.23 h118.11
M1-Board Shape:
  lines w5: 4227.16,-0.55 4227.16,250.58 ; 4227.16,0 0,0 0,3779.53 ; 4227.16,251.42 cw(c4227.13,286.85) 4227.16,322.28 4778.35,322.28 cw(c4778.38,286.85) 4778.35,251.42 4778.35,-0.55 ; 4778.35,0 5905.51,0 ; 0,3779.53 5905.51,3779.53 5905.51,0 ; 0,3779.53 0,3779.53 ; 0,3779.53 0,3779.53 ; 5905.51,0 5905.51,0
M2-Board Dimensions:
  text ".Layer_Name" at 1230.19,-1194.98 h118.11
  text ".GM2" at 2871.72,-1194.98 h118.11
M14-Top Assembly:
  text ".Layer_Name" at 1230.19,-1194.98 h118.11
  text ".GM14" at 2871.72,-1194.98 h118.11
M15-Bottom Assembly:
  text ".GM15" at 2430.65,-1196.23 h118.11
  text ".Layer_Name" at 4057.18,-1196.23 h118.11
Drill Drawing:
  drawing of 1259 lines, arcs and shapes, not listed
  text "4" at 6742.7,7226.7 h75
  text "4" at 6742.7,7226.7 h75
  text "LAYER STUCK-UP" at 6942.7,7226.7 h75
  text "LAYER STUCK-UP" at 6942.7,7226.7 h75
  text "SOLDERMASK & SILKSCREEN" at 8702.7,6986.7 h60
  text "SOLDERMASK & SILKSCREEN" at 8702.7,6986.7 h60
  text "TOP     (0.5 oz cu+planted)" at 8702.7,6866.7 h60
  text "TOP     (0.5 oz cu+planted)" at 8702.7,6866.7 h60
  text "PREPREG  3.9 mil" at 7382.7,6701.7 h60
  text "PREPREG  3.9 mil" at 7382.7,6701.7 h60
  text "5" at 53,6600 h100
  text "5" at 53,6600 h100
  text "IMPEDANCE TABLE" at 363,6580 h100
  text "IMPEDANCE TABLE" at 363,6580 h100
  text "LAYER 2 (1 oz)" at 8702.7,6566.7 h60
  text "LAYER 2 (1 oz)" at 8702.7,6566.7 h60
  text "CORE     4  mil" at 7382.7,6466.7 h60
  text "CORE     4  mil" at 7382.7,6466.7 h60
  text "LAYER 3 (1 oz)" at 8702.7,6366.7 h60
  text "LAYER 3 (1 oz)" at 8702.7,6366.7 h60
  text "63 mil" at 6510.7,6294.2 h75
  text "63 mil" at 6510.7,6294.2 h75
  text "LAYER" at 288,6286 h75
  text "LAYER" at 288,6286 h75
  text "TOLERANCE" at 4038,6286 h75
  text "TOLERANCE" at 4038,6286 h75
  text "TRACE" at 1038,6276 h75
  text "TRACE" at 1038,6276 h75
  text "SPACEING" at 1588,6276 h75
  text "SPACEING" at 1588,6276 h75
  text "IMPEDANCE" at 2338,6276 h75
  text "IMPEDANCE" at 2338,6276 h75
  text "IMPEDANCE" at 3238,6276 h75
  text "IMPEDANCE" at 3238,6276 h75
  text "PREPREG  ** mil" at 7382.7,6201.7 h60
  text "PREPREG  ** mil" at 7382.7,6201.7 h60
  text "+/-10%" at 6552.7,6186.7 h50
  text "+/-10%" at 6552.7,6186.7 h50
  text "(mil)" at 1088,6186 h50
  text "(mil)" at 1088,6186 h50
  text "(Single end)" at 2388,6186 h50
  text "(Single end)" at 2388,6186 h50
  text "(mil)" at 1688,6176 h50
  text "(mil)" at 1688,6176 h50
  text "(Differential)" at 3238,6176 h50
  text "(Differential)" at 3238,6176 h50
  text "LAYER 4 (1 oz)" at 8702.7,6066.7 h60
  text "LAYER 4 (1 oz)" at 8702.7,6066.7 h60
  text "1,6" at 283,6040 h75
  text "1,6" at 283,6040 h75
  text "5.0" at 1083,6030 h75
  text "5.0" at 1083,6030 h75
  text "N/A" at 1738,5976 h75
  text "N/A" at 1738,5976 h75
  text "CORE     4  mil" at 7382.7,5966.7 h60
  text "CORE     4  mil" at 7382.7,5966.7 h60
  text "55 OHM" at 2388,5966 h75
  text "55 OHM" at 2388,5966 h75
  text "N/A" at 3388,5966 h75
  text "N/A" at 3388,5966 h75
  text "+/-10%" at 4138,5966 h75
  text "+/-10%" at 4138,5966 h75
  text "4.0" at 1073,5910 h75
  text "4.0" at 1073,5910 h75
  text "3" at 283,5900 h75
  text "LAYER 5 (1 oz)" at 8702.7,5866.7 h60
  text "LAYER 5 (1 oz)" at 8702.7,5866.7 h60
  text "1,6" at 278,5775 h75
  text "6.1" at 1068,5775 h75
  text "8.9" at 1718,5775 h75
  text "N/A" at 2493,5730 h75
  text "90 OHM" at 3303,5720 h75
  text "+/-10%" at 4138,5716 h75
  text "+/-10%" at 4138,5716 h75
  text "PREPREG  3.9 mil" at 7382.7,5701.7 h60
  text "PREPREG  3.9 mil" at 7382.7,5701.7 h60
  text "5.1" at 1068,5665 h75
  text "9.9" at 1718,5665 h75
  text "3" at 279,5654 h75
  text "BOTTOM  (0.5 oz cu+planted)" at 8702.7,5566.7 h60
  text "BOTTOM  (0.5 oz cu+planted)" at 8702.7,5566.7 h60
  text "90 OHM" at 3297,5474 h75
  text "+/-10%" at 4144,5472 h75
  text "N/A" at 2498,5451 h75
  text "SOLDERMASK & SILKSCREEN" at 8702.7,5446.7 h60
  text "SOLDERMASK & SILKSCREEN" at 8702.7,5446.7 h60
  text "6 LAYER STACKING" at 7322.7,5266.7 h75
  text "6 LAYER STACKING" at 7322.7,5266.7 h75
  text "PCB SPECIFICATIONS :" at 6572.86,4802.21 h118.11
  text "PCB : TYPE 3" at 12379.62,4795.43 h118.11
  text "A.   MATERIAL :" at 6572.86,4644.73 h118.11
  text "FR-4" at 8088.61,4644.73 h118.11
  text "TG-170" at 8738.22,4644.73 h118.11
  text "X  TG-150" at 9456.72,4644.73 h118.11
  text "TG-140" at 10086.64,4644.73 h118.11
  text "ASPECT-RATIO, AXE Z :" at 12379.62,4578.89 h118.11
  text "B.   MATERIAL FAMILY :" at 6572.86,4526.62 h118.11
  text "N/A" at 8088.61,4526.62 h118.11
  text "C.   SOLDERMASK COLOR :" at 6572.86,4408.51 h118.11
  text "GREEN" at 8088.61,4408.51 h118.11
  text "WHITE" at 8738.22,4408.51 h118.11
  text "RED" at 9456.72,4408.51 h118.11
  text "BLACK" at 10086.64,4408.51 h118.11
  text "X  Blue ink PANTONE 2955" at 10746.03,4407 h118.11
  text "6:1 to 8:1" at 12380.36,4313.24 h118.11
  text "D.   SILKSCREEN COLOR :" at 6572.86,4290.4 h118.11
  text "X  WHITE" at 8088.61,4290.4 h118.11
  text "YELLOW" at 8738.22,4290.4 h118.11
  text "BLACK" at 9456.72,4290.4 h118.11
  text "Blue ink PANTONE 2955" at 10086.64,4290.4 h118.11
  text "E.   SURFACE FINISH :" at 6572.86,4172.29 h118.11
  text "X  ENIG" at 8088.61,4172.29 h118.11
  text "IMMERSION SILVER" at 8738.22,4172.29 h118.11
  text "IMMERSION TIN" at 10086.64,4172.29 h118.11
  text "MINIMUM PARAMETERS" at 12381.42,4092.73 h118.11
  text "HASL" at 8088.61,4054.18 h118.11
  text "HASL (PB-FREE)" at 8738.22,4054.18 h118.11
  text "GOLDEN FINGER" at 10086.64,4054.18 h118.11
  text "F.   IMPEDANCE CONTROL :" at 6572.86,3936.07 h118.11
  text "X   NO" at 8088.61,3936.07 h118.11
  text "YES  (SEE IMPEDANCE TABLE FOR DETAIL INFORMATION)" at 8738.22,3936.07 h118.11
  text "DEFAULT" at 12381.42,3876.19 h118.11
  text "G.   THROUGH VIA :" at 6572.86,3817.96 h118.11
  text "PLUG THE VIAS WHICH ARE COVERED WITH SOLDERMASK ONE OR TWO SIDE." at 8088.61,3817.96 h118.11
  text "PLUG MATERIAL :" at 8088.61,3699.85 h118.11
  text "X  SOLDERMASK" at 9092.55,3699.85 h118.11
  text "NON-CONDUCTIVE EPOXY." at 10086.64,3699.85 h118.11
  text "TRACKS : 0.127mm" at 12381.42,3649.82 h118.11
  text "H.   STACK-UP :" at 6572.86,3581.74 h118.11
  text "SEE LAYER STACK-UP SEQUENCE FOR OVERALL THICKNESS." at 8088.61,3581.74 h118.11
  text "Symbol" at 6623.5,3016.94 h72
  text "Count" at 7129.38,3016.94 h72
  text "Hole Size" at 7779.2,3016.94 h72
  text "Plated" at 8928.86,3016.94 h72
  text "Hole Type" at 9434.74,3016.94 h72
  text "Drill Layer Pair" at 10168.54,3016.94 h72
  text "Via/Pad" at 11668.09,3016.94 h72
  text "Pad Shape" at 12257.94,3016.94 h72
  text "Template" at 13003.74,3016.94 h72
  text "Description" at 14683.23,3016.94 h72
  text "Hole Tolerance (+)" at 15536.99,3016.94 h72
  text "Hole Tolerance (-)" at 16870.6,3016.94 h72
  text "1" at 7129.38,2866.94 h60
  text "19.69mil (0.500mm)" at 7779.2,2866.94 h60
  text "NPTH" at 8928.86,2866.94 h60
  text "Round" at 9434.74,2866.94 h60
  text "Top Layer - Bottom Layer" at 10168.54,2866.94 h60
  text "Pad" at 11668.09,2866.94 h60
  text "Rounded" at 12257.94,2866.94 h60
  text "c0hn50m55" at 13003.74,2866.94 h60
  text "1" at 7129.38,2716.94 h60
  text "27.56mil (0.700mm)" at 7779.2,2716.94 h60
  text "NPTH" at 8928.86,2716.94 h60
  text "Round" at 9434.74,2716.94 h60
  text "Top Layer - Bottom Layer" at 10168.54,2716.94 h60
  text "Pad" at 11668.09,2716.94 h60
  text "Rounded" at 12257.94,2716.94 h60
  text "c0hn70m75" at 13003.74,2716.94 h60
  text "2" at 7129.38,2566.94 h60
  text "27.56mil (0.700mm)" at 7779.2,2566.94 h60
  text "PTH" at 8928.86,2566.94 h60
  text "Slot" at 9434.74,2566.94 h60
  text "Top Layer - Bottom Layer" at 10168.54,2566.94 h60
  text "Pad" at 11668.09,2566.94 h60
  text "Rounded" at 12257.94,2566.94 h60
  text "r280_130h70_220r100m285_135" at 13003.74,2566.94 h60
  text "H" at 6594.41,2556.95 h66.67
  text "2" at 7129.38,2416.94 h60
  text "33.47mil (0.850mm)" at 7779.2,2416.94 h60
  text "NPTH" at 8928.86,2416.94 h60
  text "Round" at 9434.74,2416.94 h60
  text "Top Layer - Bottom Layer" at 10168.54,2416.94 h60
  text "Pad" at 11668.09,2416.94 h60
  text "Rounded" at 12257.94,2416.94 h60
  text "c0hn85m90(Tol5-5)" at 13003.74,2416.94 h60
  text "1.97mil (0.050mm)" at 15536.99,2416.94 h60
  text "1.97mil (0.050mm)" at 16870.6,2416.94 h60
  text "2" at 7129.38,2266.94 h60
  text "78.74mil (2.000mm)" at 7779.2,2266.94 h60
  text "NPTH" at 8928.86,2266.94 h60
  text "Round" at 9434.74,2266.94 h60
  text "Top Layer - Bottom Layer" at 10168.54,2266.94 h60
  text "Pad" at 11668.09,2266.94 h60
  text "Rounded" at 12257.94,2266.94 h60
  text "c50hn200m210" at 13003.74,2266.94 h60
  text "C" at 6594.41,2256.95 h66.67
  text "3" at 7129.38,2116.94 h60
  text "25.59mil (0.650mm)" at 7779.2,2116.94 h60
  text "NPTH" at 8928.86,2116.94 h60
  text "Slot" at 9434.74,2116.94 h60
  text "Top Layer - Bottom Layer" at 10168.54,2116.94 h60
  text "Pad" at 11668.09,2116.94 h60
  text "Rounded" at 12257.94,2116.94 h60
  text "(Mixed)" at 13003.74,2116.94 h60
  text "3" at 7129.38,1966.94 h60
  text "43.31mil (1.100mm)" at 7779.2,1966.94 h60
  text "NPTH" at 8928.86,1966.94 h60
  text "Round" at 9434.74,1966.94 h60
  text "Top Layer - Bottom Layer" at 10168.54,1966.94 h60
  text "Pad" at 11668.09,1966.94 h60
  text "Rounded" at 12257.94,1966.94 h60
  text "c0hn110m115" at 13003.74,1966.94 h60
  text "4" at 7129.38,1816.94 h60
  text "25.59mil (0.650mm)" at 7779.2,1816.94 h60
  text "NPTH" at 8928.86,1816.94 h60
  text "Round" at 9434.74,1816.94 h60
  text "Top Layer - Bottom Layer" at 10168.54,1816.94 h60
  text "Pad" at 11668.09,1816.94 h60
  text "Rounded" at 12257.94,1816.94 h60
  text "(Mixed)" at 13003.74,1816.94 h60
  text "4" at 7129.38,1666.94 h60
  text "67.32mil (1.710mm)" at 7779.2,1666.94 h60
  text "NPTH" at 8928.86,1666.94 h60
  text "Round" at 9434.74,1666.94 h60
  text "Top Layer - Bottom Layer" at 10168.54,1666.94 h60
  text "Pad" at 11668.09,1666.94 h60
  text "Rounded" at 12257.94,1666.94 h60
  text "c0hn171m176(Tol1-1)" at 13003.74,1666.94 h60
  text "0.39mil (0.010mm)" at 15536.99,1666.94 h60
  text "0.39mil (0.010mm)" at 16870.6,1666.94 h60
  text "4" at 7129.38,1516.94 h60
  text "137.79mil (3.500mm)" at 7779.2,1516.94 h60
  text "PTH" at 8928.86,1516.94 h60
  text "Round" at 9434.74,1516.94 h60
  text "Top Layer - Bottom Layer" at 10168.54,1516.94 h60
  text "Pad" at 11668.09,1516.94 h60
  text "Rounded" at 12257.94,1516.94 h60
  text "c700h350m705" at 13003.74,1516.94 h60
  text "4" at 7129.38,1366.94 h60
  text "177.17mil (4.500mm)" at 7779.2,1366.94 h60
  text "PTH" at 8928.86,1366.94 h60
  text "Round" at 9434.74,1366.94 h60
  text "Top Layer - Bottom Layer" at 10168.54,1366.94 h60
  text "Pad" at 11668.09,1366.94 h60
  text "Rounded" at 12257.94,1366.94 h60
  text "c900h450m905" at 13003.74,1366.94 h60
  text "A" at 6594.41,1356.95 h66.67
  text "9" at 7129.38,1216.94 h60
  text "11.81mil (0.300mm)" at 7779.2,1216.94 h60
  text "PTH" at 8928.86,1216.94 h60
  text "Round" at 9434.74,1216.94 h60
  text "Top Layer - Bottom Layer" at 10168.54,1216.94 h60
  text "Via" at 11668.09,1216.94 h60
  text "Rounded" at 12257.94,1216.94 h60
  text "v60h30" at 13003.74,1216.94 h60
  text "D" at 6594.41,1206.95 h66.67
  text "12" at 7129.38,1066.94 h60
  text "19.69mil (0.500mm)" at 7779.2,1066.94 h60
  text "PTH" at 8928.86,1066.94 h60
  text "Slot" at 9434.74,1066.94 h60
  text "Top Layer - Bottom Layer" at 10168.54,1066.94 h60
  text "Pad" at 11668.09,1066.94 h60
  text "Rounded" at 12257.94,1066.94 h60
  text "(Mixed)" at 13003.74,1066.94 h60
  text "12" at 7129.38,916.94 h60
  text "43.31mil (1.100mm)" at 7779.2,916.94 h60
  text "PTH" at 8928.86,916.94 h60
  text "Round" at 9434.74,916.94 h60
  text "Top Layer - Bottom Layer" at 10168.54,916.94 h60
  text "Pad" at 11668.09,916.94 h60
  text "(Mixed)" at 12257.94,916.94 h60
  text "(Mixed)" at 13003.74,916.94 h60
  text "13" at 7129.38,766.94 h60
  text "39.37mil (1.000mm)" at 7779.2,766.94 h60
  text "PTH" at 8928.86,766.94 h60
  text "Round" at 9434.74,766.94 h60
  text "Top Layer - Bottom Layer" at 10168.54,766.94 h60
  text "Pad" at 11668.09,766.94 h60
  text "Rounded" at 12257.94,766.94 h60
  text "(Mixed)" at 13003.74,766.94 h60
  text "23" at 7129.38,616.94 h60
  text "35.43mil (0.900mm)" at 7779.2,616.94 h60
  text "PTH" at 8928.86,616.94 h60
  text "Round" at 9434.74,616.94 h60
  text "Top Layer - Bottom Layer" at 10168.54,616.94 h60
  text "Pad" at 11668.09,616.94 h60
  text "(Mixed)" at 12257.94,616.94 h60
  text "(Mixed)" at 13003.74,616.94 h60
  text "32" at 7129.38,466.94 h60
  text "27.56mil (0.700mm)" at 7779.2,466.94 h60
  text "PTH" at 8928.86,466.94 h60
  text "Round" at 9434.74,466.94 h60
  text "Top Layer - Bottom Layer" at 10168.54,466.94 h60
  text "Pad" at 11668.09,466.94 h60
  text "(Mixed)" at 12257.94,466.94 h60
  text "(Mixed)" at 13003.74,466.94 h60
  text "61" at 7129.38,316.94 h60
  text "12.00mil (0.305mm)" at 7779.2,316.94 h60
  text "PTH" at 8928.86,316.94 h60
  text "Round" at 9434.74,316.94 h60
  text "Top Layer - Bottom Layer" at 10168.54,316.94 h60
  text "Via" at 11668.09,316.94 h60
  text "Rounded" at 12257.94,316.94 h60
  text "v61h30m0mx0" at 13003.74,316.94 h60
  text "B" at 6594.41,306.95 h66.67
  text "311" at 7129.38,166.94 h60
  text "8.00mil (0.203mm)" at 7779.2,166.94 h60
  text "PTH" at 8928.86,166.94 h60
  text "Round" at 9434.74,166.94 h60
  text "Top Layer - Bottom Layer" at 10168.54,166.94 h60
  text "Via" at 11668.09,166.94 h60
  text "Rounded" at 12257.94,166.94 h60
  text "v41h20m0mx0" at 13003.74,166.94 h60
  text "819" at 7129.38,16.94 h60
  text "10.00mil (0.254mm)" at 7779.2,16.94 h60
  text "PTH" at 8928.86,16.94 h60
  text "Round" at 9434.74,16.94 h60
  text "Top Layer - Bottom Layer" at 10168.54,16.94 h60
  text "Via" at 11668.09,16.94 h60
  text "Rounded" at 12257.94,16.94 h60
  text "(Mixed)" at 13003.74,16.94 h60
  text "1322 Total" at 7129.38,-133.06 h60
  text "Slot definitions :" at 6623.5,-278.03 h60
  text "Routed Path Length" at 7656.19,-278.03 h60
  text "= Calculated from tool start centre position to tool end centre position." at 8758.86,-278.03 h60
  text "Hole Length" at 7656.19,-378.01 h60
  text "= Routed Path Length + Tool Size = Slot length as defined in the PCB layout" at 8348.99,-378.01 h60
  text ".Layer_Name" at 1230.19,-1194.98 h118.11
  text ".DRL" at 2871.72,-1194.98 h118.11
